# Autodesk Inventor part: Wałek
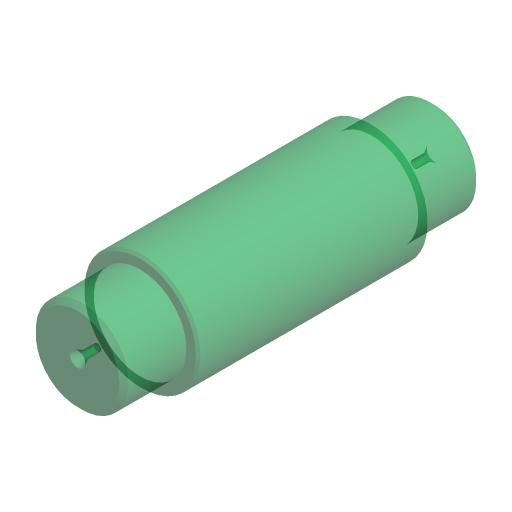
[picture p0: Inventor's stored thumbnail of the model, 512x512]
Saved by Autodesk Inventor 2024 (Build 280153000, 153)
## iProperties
Company: ATC
Shininess: 20.0
Length Units: 11269
Angle Units: 11279
Time Units: 11290
Mass Units: 11283
Length Display Precision: 3
Angle Display Precision: 2
Compacted: True
Created: 2023-03
Part Number: Wałek
Document SubType Name: Modeling
Designer: Andrzej Jaskulski
Material: Kurs-AJ
Density: 1 g/cm^3
Mass: 32.9189 g
Surface Area: 65.2455 cm^2
Volume: 32.9189 cm^3
Appearance: Przezroczyste - zielone 1
Checked By: A.J.
Engr Approved By: Andrzej Jaskulski
Mfg Approved By: Andrzej Jaskulski
Authority: A.J.
Density: 0.0
Volumn: 0.0
Area: 0.0
PropertySet Name: Model Information
Control State: 0
Master: False
Checked Out: False
Title: A.J.: Kurs R2024-MEP
Author: Andrzej Jaskulski
Revision Number: 1/24
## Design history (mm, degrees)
workplane "Work Plane2"
node "Hole1" dims "d9" = 1.6, "d10" = 3.35, "d11" = 2, "d12" = 60 deg, "d13" = 4.3, "d14" = 120 deg, "d30" = 6
node "Mirror1"
node "Chamfer1" dims "d15" = 1, "d16" = 1, "d31" = 45 deg
node "Chamfer2" dims "d17" = 0.5, "d18" = 0.5, "d32" = 45 deg
node "Bryła1"
  node "Extrusion1" dims "d1" = 50, "d2" = 0
  node "Extrusion2" dims "d5" = 13.5, "d6" = 0
workaxis "Work Axis1"
node "Korpusy bryłowe"
node "Korpusy powierzchniowe"
sketch "Sketch1"
  geometry: C1 r 12.5 at (0, 0)
  constraints: 1 centre point
  dimensions: "d3" = 25 diameter of C1
sketch "Sketch2"
  geometry: C1 r 12.5 at (0, 0) reference; C2 r 10 at (0, 0)
  constraints: 1 centre point, 1 coincident
  dimensions: "d4" = 20 diameter of C2
sketch "Sketch3"
  geometry: C1 r 10 at (0, 0) reference; 1 further point
  constraints: 1 coincident
other parameters: "d8" = -25, "d24" = 45 (derived)
